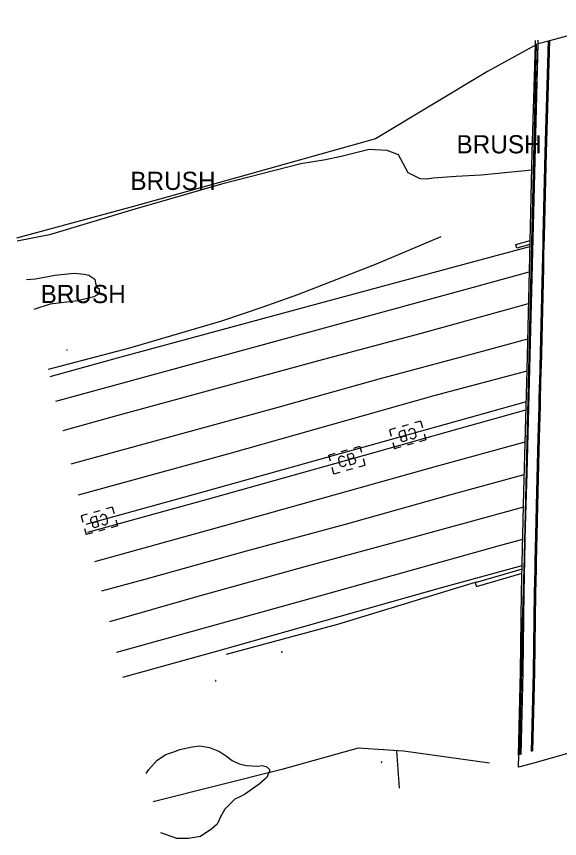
# Model space of a CAD drawing. Extents: x 2129547 to 2134906, y 657330 to 659734.
# Drawn here: x 2129547.3 to 2129756.3, y 657607.2 to 657923.4 of the extents above; entities that cross this region are included whole.
import ezdxf

# ---------------------------------------------------------------- set-up
doc = ezdxf.new("R2010")
doc.units = 0
for name, color, linetype in [('BR_X_SV_Deck_Top', 7, 'Continuous'), ('Default', 7, 'Continuous'), ('DR_X_Cells', 7, 'Continuous'), ('LT_X_Poles', 7, 'Continuous'), ('PM_X_Edge_Line', 7, 'Continuous'), ('PM_X_Lane_Line', 7, 'Continuous'), ('PV_X_Curb', 7, 'Continuous'), ('PV_X_EOP2', 7, 'Continuous'), ('PV_X_Shoulder', 7, 'Continuous'), ('RD_X_Concrete_Barrier', 7, 'Continuous'), ('RD_X_Fence', 7, 'Continuous'), ('RD_X_GR_Rt', 7, 'Continuous'), ('RD_X_Wall', 7, 'Continuous'), ('SN_X_Public', 7, 'Continuous'), ('UT_X_Unknown_Cells', 7, 'Continuous'), ('VG_X_Shrub_Line_Lt', 7, 'Continuous'), ('VG_X_Text', 7, 'Continuous'), ('VG_X_Tree_Line_Lt', 7, 'Continuous')]:
    doc.layers.add(name, color=color, linetype=linetype)

# ---------------------------------------------------------------- blocks, each defined once
blk = doc.blocks.new('POINT_DISPLAY')
at = {"layer": 'Default'}
blk.add_line((0, 0), (0, 0), dxfattribs=at)
blk = doc.blocks.new('GCB-X')
at = {"layer": 'Default'}
for p, q in [((-0.0317, 0.019), (-0.019, 0.019)), ((-0.0317, 0.0063), (-0.0317, 0.019)), ((-0.0063, 0.019), (0.0063, 0.019)), ((0.019, 0.019), (0.0317, 0.019)), ((0.0317, 0.0063), (0.0317, 0.019)), ((0.0034, 0.0007), (0.0124, 0.0007)), ((-0.0317, -0.019), (-0.0317, -0.0063)), ((0.0317, -0.019), (0.0317, -0.0063)), ((-0.0317, -0.019), (-0.019, -0.019)), ((-0.0063, -0.019), (0.0063, -0.019)), ((0.019, -0.019), (0.0317, -0.019))]:
    blk.add_line(p, q, dxfattribs=at)
blk.add_lwpolyline([(0.0116, 0.0099), (0.0034, 0.0099), (0.0034, -0.0104), (0.0124, -0.0104)], dxfattribs=at)
for centre, radius, start, end in [((0.0071, 0), 0.0233, 164.8107, 195.1893), ((-0.0094, 0.0037), 0.00645, 21.5603, 158.4397), ((0.0101, 0.0051), 0.00501, 296.8207, 73.0013), ((0.0101, -0.0049), 0.00597, 292.0547, 67.9453), ((-0.0094, -0.0037), 0.00645, 201.5603, 338.4397)]:
    blk.add_arc(centre, radius, start, end, dxfattribs=at)
for p in [(0, 0.019), (0, 0.019), (-0.0317, 0), (0, 0), (0, 0), (0, 0), (0.0317, 0), (0, -0.019), (0, -0.019)]:
    blk.add_blockref('POINT_DISPLAY', p, dxfattribs=at)

msp = doc.modelspace()

# ---------------------------------------------------------------- linework, layer by layer
at = {"layer": 'BR_X_SV_Deck_Top'}
msp.add_lwpolyline([(2129740.51, 657634.62), (2129741.87, 657685.89), (2129743.83, 657747.88), (2129748.02, 657912.97), (2129752.03, 657914.04), (2129752.54, 657914.17), (2129766.42, 657917.87), (2129780.56, 657921.96), (2129781.07, 657922.1), (2129785.55, 657923.4), (2129784.29, 657858.35), (2129782.53, 657795.25), (2129779.4, 657645.64), (2129774.6, 657644.27), (2129774.09, 657644.13), (2129759.88, 657640.06), (2129745.88, 657636.13), (2129745.37, 657635.99)], close=True, dxfattribs=at)
at = {"layer": 'LT_X_Poles'}
msp.add_lwpolyline([(2129687.82, 657636.82), (2129687.74, 657636.52), (2129687.86, 657636.52)], dxfattribs=at)
msp.add_circle((2129687.78, 657636.67), 0.065, dxfattribs=at)
at = {"layer": 'PM_X_Edge_Line'}
for points in [[(2129562.55, 657775.4), (2129622.57, 657791.87), (2129721.75, 657818.9), (2129744.63, 657825.2)], [(2129571.27, 657739.45), (2129629.12, 657755.24), (2129708.09, 657777.56), (2129743.75, 657787.12)], [(2129577.5, 657713.77), (2129626.98, 657727.45), (2129708.9, 657750.47), (2129743, 657759.8)], [(2129585.97, 657678.88), (2129657.98, 657698.84), (2129733.11, 657719.9), (2129742.1, 657722.35)]]:
    msp.add_lwpolyline(points, dxfattribs=at)
at = {"layer": 'PM_X_Lane_Line'}
for points in [[(2129565.28, 657764.14), (2129585.1, 657769.66), (2129623.65, 657780.15), (2129663.67, 657791.03), (2129703.17, 657801.62), (2129744.35, 657813.03)], [(2129568.4, 657751.28), (2129608.67, 657762.38), (2129648.04, 657773.15), (2129686.86, 657783.98), (2129726.67, 657794.69), (2129744.03, 657799.43)], [(2129580.25, 657702.46), (2129596.37, 657706.86), (2129636.3, 657718), (2129673.9, 657728.09), (2129714.08, 657739.38), (2129742.66, 657747.27)], [(2129742.35, 657734.63), (2129697.52, 657722.31), (2129657.8, 657711.54), (2129616.2, 657700.05), (2129583.13, 657690.57)]]:
    msp.add_lwpolyline(points, dxfattribs=at)
at = {"layer": 'PV_X_Curb'}
msp.add_lwpolyline([(2129745.49, 657640.66), (2129746.28, 657671.2), (2129746.67, 657701.77), (2129746.86, 657710.72), (2129746.89, 657712.28), (2129746.92, 657713.68), (2129747.13, 657723.72), (2129747.48, 657740.62), (2129748.04, 657761.18), (2129748.38, 657773.44), (2129748.46, 657776.58), (2129748.75, 657787.22), (2129748.78, 657788.47), (2129749.67, 657826.59), (2129749.77, 657830.89), (2129749.9, 657836.36), (2129749.91, 657837.04), (2129749.95, 657838.61), (2129750.73, 657871.04), (2129752.03, 657914.04)], dxfattribs=at)
at = {"layer": 'PV_X_EOP2'}
for points in [[(2129746, 657640.8), (2129746.78, 657671.19), (2129747.17, 657701.77), (2129747.36, 657710.86), (2129747.39, 657712.42), (2129747.42, 657713.82), (2129747.63, 657723.86), (2129747.98, 657740.61), (2129748.54, 657761.32), (2129748.88, 657773.58), (2129748.96, 657776.72), (2129749.25, 657787.21), (2129749.28, 657788.61), (2129750.17, 657826.73), (2129750.27, 657830.87), (2129750.4, 657836.49), (2129750.42, 657837.18), (2129750.46, 657838.75), (2129751.23, 657871.03), (2129752.54, 657914.17)], [(2129562.55, 657775.4), (2129622.57, 657791.87), (2129721.75, 657818.9), (2129744.63, 657825.2)], [(2129571.27, 657739.45), (2129629.12, 657755.24), (2129708.09, 657777.56), (2129743.75, 657787.12)], [(2129577.5, 657713.77), (2129626.98, 657727.45), (2129708.9, 657750.47), (2129743, 657759.8)], [(2129585.97, 657678.88), (2129657.98, 657698.84), (2129733.11, 657719.9), (2129742.1, 657722.35)]]:
    msp.add_lwpolyline(points, dxfattribs=at)
at = {"layer": 'PV_X_Shoulder'}
for points in [[(2129560.25, 657784.86), (2129586.22, 657792.1), (2129663.94, 657813.09), (2129730.49, 657831.02), (2129744.86, 657834.97)], [(2129588.3, 657669.28), (2129624.85, 657679.35), (2129711.41, 657703.85), (2129741.89, 657712.29)]]:
    msp.add_lwpolyline(points, dxfattribs=at)
at = {"layer": 'RD_X_Concrete_Barrier'}
for points in [[(2129744.88, 657835.67), (2129739.84, 657834.29), (2129739.45, 657835.74), (2129744.92, 657837.23)], [(2129743.42, 657775.18), (2129717.74, 657768.01), (2129675.42, 657756.16), (2129619.97, 657740.67), (2129574.06, 657727.94)], [(2129574.77, 657725.02), (2129620.78, 657737.78), (2129676.23, 657753.27), (2129718.55, 657765.12), (2129743.33, 657772.04)], [(2129741.86, 657710.86), (2129723.86, 657705.56), (2129724.28, 657704.12), (2129741.83, 657709.28)]]:
    msp.add_lwpolyline(points, dxfattribs=at)
at = {"layer": 'RD_X_Fence'}
for p, q in [((2129740.94, 657639.4), (2129747.43, 657912.83)), ((2129694.66, 657626.59), (2129693.68, 657640.93))]:
    msp.add_line(p, q, dxfattribs=at)
for points in [[(2129746.98, 657912.39), (2129728.58, 657902.22), (2129685.5, 657876.32), (2129633.78, 657861.8), (2129592.33, 657850.33), (2129547.34, 657838.08)], [(2129729.3, 657636.18), (2129696.23, 657640.76), (2129678.83, 657641.97), (2129649.4, 657633.79), (2129599.92, 657621.37)]]:
    msp.add_lwpolyline(points, dxfattribs=at)
at = {"layer": 'RD_X_GR_Rt'}
for points in [[(2129710.62, 657838.64), (2129685.67, 657828.16), (2129655.42, 657816.34), (2129642.11, 657811.52), (2129626.22, 657806.17), (2129590.78, 657795.8), (2129559.6, 657787.55)], [(2129628.2, 657678.09), (2129670.98, 657689.72), (2129724.34, 657705.9)]]:
    msp.add_lwpolyline(points, dxfattribs=at)
at = {"layer": 'RD_X_Wall'}
for points in [[(2129740.46, 657639.26), (2129741.28, 657671.3), (2129741.68, 657701.86), (2129742.48, 657740.74), (2129743.75, 657787.35), (2129744.77, 657831.01), (2129745.74, 657871.18), (2129746.99, 657912.68), (2129747.03, 657914.1)], [(2129741.46, 657639.54), (2129742.28, 657671.28), (2129742.67, 657701.84), (2129743.48, 657740.72), (2129744.75, 657787.32), (2129745.77, 657830.98), (2129746.73, 657871.15), (2129748, 657912.96), (2129748.04, 657914.31)]]:
    msp.add_lwpolyline(points, dxfattribs=at)
at = {"layer": 'SN_X_Public'}
for p, q in [((2129566.72, 657795.08), (2129566.65, 657795.07)), ((2129566.73, 657795.03), (2129566.65, 657795.02)), ((2129566.72, 657795.13), (2129566.74, 657794.98))]:
    msp.add_line(p, q, dxfattribs=at)
at = {"layer": 'UT_X_Unknown_Cells'}
for p, q in [((2129649.35, 657678.98), (2129649.35, 657678.92)), ((2129649.4, 657678.98), (2129649.4, 657678.92)), ((2129623.94, 657667.9), (2129623.94, 657667.84)), ((2129623.99, 657667.9), (2129623.99, 657667.84))]:
    msp.add_line(p, q, dxfattribs=at)
for points in [[(2129649.43, 657678.9), (2129649.43, 657678.98), (2129649.46, 657678.9), (2129649.49, 657678.98), (2129649.49, 657678.9)], [(2129624.01, 657667.82), (2129624.01, 657667.9), (2129624.04, 657667.82), (2129624.07, 657667.9), (2129624.07, 657667.82)]]:
    msp.add_lwpolyline(points, dxfattribs=at)
for centre, radius, start, end in [((2129649.42, 657678.94), 0.1, 160.0169, 200.0392), ((2129649.42, 657678.94), 0.1, 100.0806, 140.0721), ((2129649.42, 657678.94), 0.1, 220.0577, 260.0473), ((2129649.38, 657678.93), 0.0279, 205.1924, 334.8076), ((2129649.42, 657678.94), 0.1, 40.0577, 80.1061), ((2129649.42, 657678.94), 0.1, 280.0114, 320.0264), ((2129649.42, 657678.94), 0.1, 340.0169, 20.0392), ((2129624.01, 657667.86), 0.1, 160.0169, 200.0392), ((2129624.01, 657667.86), 0.1, 100.0806, 140.0721), ((2129624.01, 657667.86), 0.1, 220.0577, 260.0473), ((2129623.96, 657667.85), 0.0279, 205.1924, 334.8076), ((2129624.01, 657667.86), 0.1, 40.0577, 80.1061), ((2129624.01, 657667.86), 0.1, 280.0114, 320.0264), ((2129624.01, 657667.86), 0.1, 340.0169, 20.0392)]:
    msp.add_arc(centre, radius, start, end, dxfattribs=at)
at = {"layer": 'VG_X_Shrub_Line_Lt'}
for points in [[(2129745.57, 657864.28), (2129726.1, 657862.32), (2129716.51, 657861.84), (2129707.61, 657861.14), (2129705.22, 657860.76), (2129702.63, 657860.94), (2129697.98, 657863.26), (2129694.27, 657870.23), (2129689.94, 657871.8), (2129683.08, 657872.25), (2129672.24, 657869.51), (2129666.26, 657868.31), (2129656.71, 657866.72), (2129626.18, 657858.94), (2129592.94, 657849.33), (2129560.03, 657839.44), (2129547.61, 657836.97)], [(2129551.2, 657822.17), (2129554.64, 657822.48), (2129562.11, 657823.87), (2129569.56, 657824.7), (2129573.43, 657824.33), (2129575.19, 657823.84), (2129577.45, 657822.29), (2129577.7, 657820.87), (2129578.31, 657819.25), (2129579.15, 657818.59), (2129579.17, 657816.77), (2129577.1, 657815.62), (2129570.97, 657814.01), (2129560.28, 657812.74), (2129553.98, 657810.72)]]:
    msp.add_lwpolyline(points, dxfattribs=at)
at = {"layer": 'VG_X_Tree_Line_Lt'}
msp.add_lwpolyline([(2129597.3, 657632.17), (2129598.33, 657633.81), (2129601.51, 657637.31), (2129604.8, 657639.51), (2129607.93, 657640.57), (2129610.25, 657641.44), (2129614.99, 657642.5), (2129617.89, 657642.82), (2129621.66, 657642.25), (2129625.47, 657640.65), (2129628.19, 657638.85), (2129630.31, 657637.27), (2129632.96, 657635.93), (2129635.66, 657635.27), (2129640.14, 657635.11), (2129641.84, 657635.26), (2129643.45, 657634.89), (2129644.68, 657633.79), (2129644.67, 657633.13), (2129644.2, 657631.98), (2129643.7, 657630.67), (2129642.76, 657629.9), (2129640.68, 657628.17), (2129635.04, 657624.2), (2129633.32, 657623.31), (2129631.4, 657622.31), (2129629.42, 657620.43), (2129627.44, 657618.46), (2129626.32, 657616.44), (2129626.22, 657616.37), (2129624.53, 657612.7), (2129622.56, 657610.96), (2129618.09, 657608.06), (2129613.47, 657607.29), (2129609.09, 657607.21), (2129602.84, 657609.35)], dxfattribs=at)

# ---------------------------------------------------------------- block references
at = {"layer": 'DR_X_Cells'}
for p, xscale, yscale, rotation in [((2129697.81, 657762.43), 196.85000000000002, 196.85000000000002, -164.3543889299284), ((2129674.49, 657752.79), 196.85, 196.85000000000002, 15.611735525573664), ((2129579.19, 657729.36), 196.85, 196.85000000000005, -164.50514198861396)]:
    msp.add_blockref('GCB-X', p, dxfattribs=dict(at, xscale=xscale, yscale=yscale, rotation=rotation))
at = {"layer": 'SN_X_Public', "xscale": 3.9370000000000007, "yscale": 3.9370000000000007, "rotation": 8.382900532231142}
msp.add_blockref('POINT_DISPLAY', (2129566.73, 657795.05), dxfattribs=at)
at = {"layer": 'UT_X_Unknown_Cells', "xscale": 3.9370000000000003, "yscale": 3.9370000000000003}
for p in [(2129649.42, 657678.94), (2129624.01, 657667.86)]:
    msp.add_blockref('POINT_DISPLAY', p, dxfattribs=at)

# ---------------------------------------------------------------- texts
at = {"layer": 'VG_X_Text'}
for p in [(2129716.62, 657870.73), (2129591.15, 657856.67), (2129556.63, 657813.14)]:
    msp.add_text('BRUSH', height=7, dxfattribs=at).set_placement(p)

doc.saveas('drawing.dxf')
